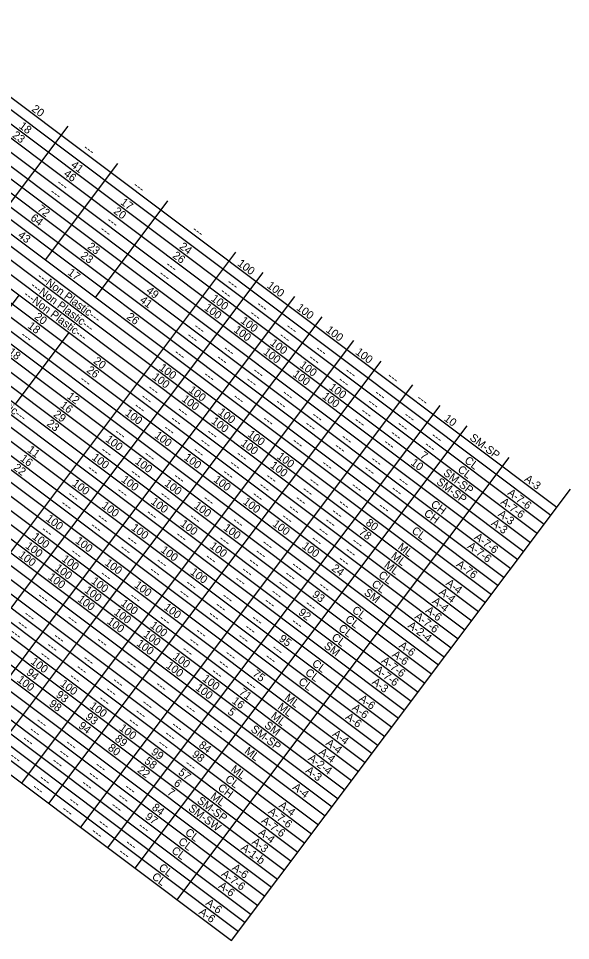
# Model space of a CAD drawing. Extents: x 627484.2 to 627514.4, y 367972.1 to 367996.9.
# Drawn here: x 627496.37 to 627500.17, y 367972.11 to 367978.45 of the extents above; entities that cross this region are included whole.
import ezdxf

# ---------------------------------------------------------------- set-up
doc = ezdxf.new("R2010")
doc.units = 0
doc.layers.add('Default', color=7, linetype='Continuous')

msp = doc.modelspace()

# ---------------------------------------------------------------- linework, layer by layer
at = {"layer": 'Default'}
for p, q in [((627495.5986, 367978.4521), (627500.0738, 367975.0916)), ((627495.5576, 367978.3975), (627500.0329, 367975.037)), ((627495.5108, 367978.3352), (627499.986, 367974.9747)), ((627495.4639, 367978.2728), (627499.9392, 367974.9123)), ((627495.4171, 367978.2104), (627499.8924, 367974.8499)), ((627495.3703, 367978.1481), (627499.8455, 367974.7876)), ((627495.3293, 367978.0935), (627499.8045, 367974.733)), ((627495.2825, 367978.0311), (627499.7577, 367974.6706)), ((627495.1946, 367977.9142), (627499.6699, 367974.5537)), ((627495.2356, 367977.9687), (627499.7109, 367974.6082)), ((627495.1478, 367977.8518), (627499.623, 367974.4913)), ((627495.1068, 367977.7972), (627499.5821, 367974.4367)), ((627495.06, 367977.7348), (627499.5352, 367974.3743)), ((627495.0131, 367977.6725), (627499.4884, 367974.312)), ((627495.0743, 367975.5294), (627496.7136, 367977.7124)), ((627494.9663, 367977.6101), (627499.4416, 367974.2496)), ((627494.9195, 367977.5477), (627499.3947, 367974.1872)), ((627494.8726, 367977.4853), (627499.3479, 367974.1248)), ((627494.8258, 367977.423), (627499.301, 367974.0625)), ((627496.559, 367976.7921), (627497.0566, 367977.4548)), ((627494.7848, 367977.3684), (627499.2601, 367974.0079)), ((627494.738, 367977.306), (627499.2132, 367973.9455)), ((627494.6911, 367977.2437), (627499.1664, 367973.8831)), ((627494.6443, 367977.1813), (627499.1196, 367973.8208)), ((627496.902, 367976.5345), (627497.3997, 367977.1972)), ((627494.5975, 367977.1189), (627499.0727, 367973.7584)), ((627494.5506, 367977.0565), (627499.0259, 367973.696)), ((627494.5097, 367977.002), (627498.9849, 367973.6415)), ((627494.4628, 367976.9396), (627498.9381, 367973.5791)), ((627494.416, 367976.8772), (627498.8912, 367973.5167)), ((627496.2282, 367974.6629), (627497.8675, 367976.846)), ((627494.3691, 367976.8148), (627498.8444, 367973.4543)), ((627494.3282, 367976.7603), (627498.8034, 367973.3998)), ((627496.4153, 367974.5224), (627498.0546, 367976.7054)), ((627494.2813, 367976.6979), (627498.7566, 367973.3374)), ((627494.2345, 367976.6355), (627498.7097, 367973.275)), ((627494.1877, 367976.5731), (627498.6629, 367973.2126)), ((627496.0087, 367976.0592), (627496.3775, 367976.5504)), ((627496.6336, 367974.3585), (627498.2729, 367976.5415)), ((627494.1408, 367976.5108), (627498.6161, 367973.1503)), ((627494.053, 367976.3938), (627498.5282, 367973.0333)), ((627494.094, 367976.4484), (627498.5692, 367973.0879)), ((627496.8207, 367974.218), (627498.46, 367976.401)), ((627494.0062, 367976.3314), (627498.4814, 367972.9709)), ((627493.9593, 367976.2691), (627498.4346, 367972.9086)), ((627496.3517, 367975.8016), (627496.7205, 367976.2928)), ((627493.9125, 367976.2067), (627498.3877, 367972.8462)), ((627497.039, 367974.054), (627498.6783, 367976.2371)), ((627493.8657, 367976.1443), (627498.3409, 367972.7838)), ((627493.8188, 367976.082), (627498.2941, 367972.7215)), ((627497.2262, 367973.9135), (627498.8654, 367976.0966)), ((627493.772, 367976.0196), (627498.2472, 367972.6591)), ((627493.7251, 367975.9572), (627498.2004, 367972.5967)), ((627493.6783, 367975.8948), (627498.1536, 367972.5343)), ((627497.4445, 367973.7496), (627499.0837, 367975.9326)), ((627493.6373, 367975.8403), (627498.1126, 367972.4798)), ((627493.5905, 367975.7779), (627498.0657, 367972.4174)), ((627497.6316, 367973.6091), (627499.2709, 367975.7921)), ((627493.5437, 367975.7155), (627498.0189, 367972.355)), ((627493.4968, 367975.6531), (627497.9721, 367972.2926)), ((627497.8187, 367973.4686), (627499.458, 367975.6516)), ((627493.4558, 367975.5986), (627497.9311, 367972.2381)), ((627493.409, 367975.5362), (627497.8842, 367972.1757)), ((627493.3622, 367975.4738), (627497.8374, 367972.1133)), ((627498.1072, 367973.252), (627499.7464, 367975.435)), ((627498.4814, 367972.9709), (627500.1675, 367975.2164)), ((627495.7713, 367973.6648), (627496.4153, 367974.5224)), ((627495.9896, 367973.5008), (627496.6336, 367974.3585)), ((627496.1767, 367973.3603), (627496.8207, 367974.218)), ((627496.395, 367973.1964), (627497.039, 367974.054)), ((627496.5822, 367973.0559), (627497.2262, 367973.9135)), ((627496.8005, 367972.892), (627497.4445, 367973.7496)), ((627496.9876, 367972.7515), (627497.6316, 367973.6091)), ((627497.1747, 367972.611), (627497.8187, 367973.4686)), ((627497.7719, 367973.4062), (627498.4346, 367972.9086)), ((627497.4632, 367972.3943), (627498.1072, 367973.252)), ((627497.8374, 367972.1133), (627498.4814, 367972.9709))]:
    msp.add_line(p, q, dxfattribs=at)

# ---------------------------------------------------------------- texts
for s, p in [('20', (627496.4591, 367977.8204)), ('18', (627496.372, 367977.7029)), ('23', (627496.326, 367977.6399)), ('---', (627496.814, 367977.5539)), ('46', (627496.6793, 367977.3746)), ('41', (627496.7288, 367977.4349)), ('---', (627496.6325, 367977.3122)), ('---', (627497.157, 367977.2963)), ('---', (627496.5857, 367977.2498)), ('72', (627496.4979, 367977.1328)), ('20', (627497.0222, 367977.1171)), ('17', (627497.0694, 367977.1792)), ('64', (627496.4508, 367977.0706)), ('---', (627496.9755, 367977.0546)), ('43', (627496.3646, 367976.9525)), ('---', (627496.9287, 367976.9922)), ('---', (627497.5625, 367976.9918)), ('23', (627496.8423, 367976.8742)), ('24', (627497.4744, 367976.875)), ('23', (627496.7954, 367976.8118)), ('26', (627497.4277, 367976.8126)), ('100', (627497.8735, 367976.7583)), ('17', (627496.7064, 367976.6958)), ('---', (627497.3341, 367976.6878)), ('---', (627497.381, 367976.7501)), ('---Non Plastic---', (627496.4976, 367976.6697)), ('---', (627497.8021, 367976.629)), ('---Non Plastic---', (627496.4508, 367976.6073)), ('49', (627497.2464, 367976.5708)), ('---', (627497.7553, 367976.5666)), ('100', (627498.0762, 367976.606)), ('---Non Plastic---', (627496.404, 367976.5449)), ('41', (627497.2021, 367976.5064)), ('100', (627497.692, 367976.5166)), ('100', (627497.6452, 367976.4542)), ('---', (627498.0048, 367976.4768)), ('100', (627498.2789, 367976.4538)), ('20', (627496.4778, 367976.392)), ('26', (627497.1116, 367976.3915)), ('100', (627497.8947, 367976.3643)), ('---', (627497.958, 367976.4144)), ('18', (627496.4316, 367976.3291)), ('---', (627497.5738, 367976.3249)), ('100', (627497.8479, 367976.302)), ('---', (627498.2075, 367976.3245)), ('100', (627498.4816, 367976.3016)), ('---', (627496.3842, 367976.2671)), ('---', (627497.5269, 367976.2625)), ('---', (627498.1607, 367976.2622)), ('100', (627498.0974, 367976.2121)), ('18', (627496.297, 367976.1498)), ('---', (627497.4391, 367976.1456)), ('---', (627497.7765, 367976.1727)), ('100', (627498.0506, 367976.1497)), ('---', (627498.4102, 367976.1723)), ('100', (627498.6844, 367976.1494)), ('20', (627496.8832, 367976.0875)), ('100', (627497.3349, 367976.041)), ('---', (627497.7296, 367976.1103)), ('100', (627498.3002, 367976.0599)), ('---', (627498.3634, 367976.11)), ('---Non Plastic---', (627495.9883, 367975.9914)), ('26', (627496.8364, 367976.0251)), ('100', (627497.2881, 367975.9786)), ('---', (627497.6418, 367975.9934)), ('---', (627497.9792, 367976.0205)), ('100', (627498.2533, 367975.9975)), ('---', (627498.6129, 367976.0201)), ('---', (627496.7897, 367975.9627)), ('---', (627497.9324, 367975.9581)), ('---', (627498.5661, 367975.9577)), ('---', (627498.9035, 367975.9848)), ('---', (627497.2576, 367975.9039)), ('100', (627497.5376, 367975.8887)), ('---', (627498.1819, 367975.8683)), ('100', (627498.5029, 367975.9077)), ('---', (627498.8157, 367975.8679)), ('12', (627496.7019, 367975.8457)), ('---', (627497.2108, 367975.8415)), ('100', (627497.4908, 367975.8264)), ('---', (627497.8445, 367975.8412)), ('---', (627498.1351, 367975.8059)), ('100', (627498.456, 367975.8453)), ('---', (627498.7688, 367975.8055)), ('---', (627499.1062, 367975.8326)), ('29', (627496.6082, 367975.7209)), ('16', (627496.6549, 367975.7834)), ('100', (627497.1007, 367975.7291)), ('---', (627497.164, 367975.7792)), ('---', (627497.4603, 367975.7517)), ('100', (627497.7403, 367975.7365)), ('---', (627498.722, 367975.7431)), ('23', (627496.5627, 367975.6576)), ('---', (627497.4135, 367975.6893)), ('100', (627497.6935, 367975.6742)), ('---', (627498.0472, 367975.6889)), ('---', (627498.3846, 367975.716)), ('---', (627498.6751, 367975.6808)), ('---', (627499.0184, 367975.7157)), ('10', (627499.2931, 367975.6922)), ('---', (627497.3667, 367975.6269)), ('---', (627498.3378, 367975.6537)), ('---', (627498.9715, 367975.6533)), ('100', (627496.9661, 367975.5498)), ('---', (627497.0293, 367975.5998)), ('100', (627497.3034, 367975.5769)), ('---', (627497.663, 367975.5995)), ('100', (627497.943, 367975.5843)), ('---', (627498.5873, 367975.5638)), ('---', (627498.9247, 367975.5909)), ('---', (627499.2055, 367975.5752)), ('SM-SP', (627499.4696, 367975.5598)), ('11', (627496.4293, 367975.4773)), ('---', (627497.6162, 367975.5371)), ('100', (627497.8962, 367975.5219)), ('---', (627498.25, 367975.5367)), ('---', (627498.5405, 367975.5015)), ('---', (627498.8779, 367975.5286)), ('---', (627499.1586, 367975.5128)), ('16', (627496.3798, 367975.417)), ('100', (627496.8724, 367975.425)), ('---', (627496.9356, 367975.4751)), ('---', (627497.232, 367975.4476)), ('100', (627497.5061, 367975.4247)), ('---', (627497.5694, 367975.4747)), ('---', (627497.8658, 367975.4472)), ('100', (627498.1457, 367975.4321)), ('7', (627499.1282, 367975.4381)), ('CL', (627499.4337, 367975.4038)), ('22', (627496.333, 367975.3545)), ('100', (627497.1688, 367975.3976)), ('---', (627497.8189, 367975.3849)), ('100', (627498.0989, 367975.3697)), ('---', (627498.4527, 367975.3845)), ('---', (627498.79, 367975.4116)), ('10', (627499.0648, 367975.3882)), ('CL', (627499.3868, 367975.3415)), ('---', (627496.842, 367975.3503)), ('---', (627497.1383, 367975.3229)), ('---', (627497.4347, 367975.2954)), ('---', (627497.7721, 367975.3225)), ('---', (627498.0685, 367975.295)), ('---', (627498.7432, 367975.3492)), ('SM-SP', (627499.2881, 367975.3181)), ('100', (627496.7377, 367975.2457)), ('100', (627497.0751, 367975.2728)), ('100', (627497.3715, 367975.2453)), ('100', (627497.7088, 367975.2724)), ('---', (627498.0216, 367975.2327)), ('---', (627498.3649, 367975.2676)), ('---', (627498.6554, 367975.2323)), ('---', (627498.9772, 367975.2711)), ('SM-SP', (627499.2412, 367975.2557)), ('A-3', (627499.8458, 367975.2772)), ('---', (627496.7073, 367975.171)), ('---', (627497.0447, 367975.1981)), ('---', (627497.341, 367975.1707)), ('---', (627497.9748, 367975.1703)), ('---', (627498.318, 367975.2052)), ('---', (627498.9303, 367975.2087)), ('A-7-6', (627499.7295, 367975.1817)), ('---', (627496.6605, 367975.1086)), ('100', (627496.9404, 367975.0935)), ('100', (627497.2778, 367975.1206)), ('100', (627497.5742, 367975.0931)), ('---', (627497.6374, 367975.1432)), ('100', (627497.9116, 367975.1202)), ('---', (627498.2712, 367975.1428)), ('---', (627498.5676, 367975.1153)), ('CH', (627499.2017, 367975.1025)), ('A-7-6', (627499.6826, 367975.1193)), ('---', (627497.2474, 367975.0459)), ('---', (627498.2243, 367975.0804)), ('---', (627498.5207, 367975.053)), ('---', (627498.8425, 367975.0918)), ('CH', (627499.1549, 367975.0401)), ('A-3', (627499.6643, 367975.0355)), ('100', (627496.5562, 367975.004)), ('---', (627496.91, 367975.0188)), ('100', (627497.4805, 367974.9684)), ('---', (627497.5438, 367975.0184)), ('---', (627497.8401, 367974.991)), ('100', (627498.1143, 367974.968)), ('---', (627498.1775, 367975.0181)), ('---', (627498.4739, 367974.9906)), ('80', (627498.7545, 367974.9749)), ('A-3', (627499.6175, 367974.9732)), ('---', (627496.5258, 367974.9293)), ('---', (627496.8632, 367974.9564)), ('100', (627497.1432, 367974.9413)), ('100', (627497.7769, 367974.9409)), ('---', (627498.4271, 367974.9282)), ('78', (627498.7084, 367974.912)), ('CL', (627499.0707, 367974.9204)), ('100', (627496.4626, 367974.8793)), ('100', (627496.759, 367974.8518)), ('---', (627497.1127, 367974.8666)), ('---', (627497.4501, 367974.8937)), ('---', (627497.7465, 367974.8662)), ('---', (627498.3802, 367974.8658)), ('---', (627498.661, 367974.8501)), ('A-7-6', (627499.5012, 367974.8776)), ('100', (627496.4157, 367974.8169)), ('---', (627497.0659, 367974.8042)), ('100', (627497.3459, 367974.7891)), ('100', (627497.6832, 367974.8162)), ('---', (627498.0429, 367974.8387)), ('100', (627498.317, 367974.8158)), ('---', (627498.6142, 367974.7877)), ('ML', (627498.9756, 367974.8089)), ('A-7-6', (627499.4543, 367974.8153)), ('100', (627496.3689, 367974.7545)), ('100', (627496.6653, 367974.7271)), ('---', (627496.7285, 367974.7771)), ('---', (627497.6528, 367974.7415)), ('---', (627497.996, 367974.7764)), ('---', (627498.5673, 367974.7253)), ('ML', (627498.9288, 367974.7465)), ('100', (627496.6184, 367974.6647)), ('100', (627496.9617, 367974.6996)), ('---', (627497.3154, 367974.7144)), ('---', (627497.9492, 367974.714)), ('---', (627498.2456, 367974.6865)), ('24', (627498.5203, 367974.6631)), ('ML', (627498.882, 367974.6842)), ('A-76', (627499.3773, 367974.6902)), ('100', (627496.5716, 367974.6023)), ('---', (627496.9312, 367974.6249)), ('---', (627497.2686, 367974.652)), ('100', (627497.5486, 367974.6368)), ('---', (627497.9023, 367974.6516)), ('---', (627498.1987, 367974.6242)), ('CL', (627498.8423, 367974.6164)), ('100', (627496.868, 367974.5748)), ('100', (627497.1644, 367974.5474)), ('---', (627497.5181, 367974.5621)), ('---', (627497.8555, 367974.5893)), ('---', (627498.1519, 367974.5618)), ('---', (627498.4327, 367974.546)), ('CL', (627498.7955, 367974.554)), ('A-4', (627499.3056, 367974.5611)), ('---', (627496.5002, 367974.473)), ('100', (627496.8212, 367974.5125)), ('---', (627497.1339, 367974.4727)), ('---', (627497.4713, 367974.4998)), ('---', (627497.7677, 367974.4723)), ('---', (627498.1051, 367974.4994)), ('93', (627498.3872, 367974.4826)), ('SM', (627498.7432, 367974.4957)), ('A-4', (627499.2588, 367974.4988)), ('100', (627496.7743, 367974.4501)), ('100', (627497.0707, 367974.4226)), ('100', (627497.3671, 367974.3951)), ('---', (627497.7209, 367974.4099)), ('---', (627498.0582, 367974.437)), ('---', (627498.339, 367974.4213)), ('A-4', (627499.2119, 367974.4364)), ('---', (627496.4065, 367974.3483)), ('100', (627497.0239, 367974.3602)), ('---', (627497.674, 367974.3476)), ('92', (627498.2922, 367974.3589)), ('CL', (627498.6609, 367974.3747)), ('A-7-6', (627499.0913, 367974.3319)), ('A-6', (627499.1652, 367974.3739)), ('---', (627496.3597, 367974.2859)), ('---', (627496.7029, 367974.3208)), ('100', (627496.977, 367974.2979)), ('100', (627497.2734, 367974.2704)), ('---', (627497.3367, 367974.3205)), ('---', (627497.9704, 367974.3201)), ('---', (627498.2453, 367974.2965)), ('CL', (627498.614, 367974.3123)), ('A-2-4', (627499.0444, 367974.2696)), ('---', (627496.3128, 367974.2236)), ('100', (627497.2266, 367974.208)), ('---', (627497.5862, 367974.2306)), ('---', (627497.9236, 367974.2577)), ('CL', (627498.5672, 367974.2499)), ('---', (627496.6092, 367974.1961)), ('---', (627496.9056, 367974.1686)), ('100', (627497.1797, 367974.1457)), ('---', (627497.5394, 367974.1682)), ('---', (627497.8767, 367974.1953)), ('95', (627498.1583, 367974.179)), ('CL', (627498.5203, 367974.1876)), ('---', (627496.5624, 367974.1337)), ('---', (627497.4925, 367974.1059)), ('---', (627498.1107, 367974.1172)), ('SM', (627498.4681, 367974.1293)), ('A-6', (627498.9837, 367974.1322)), ('100', (627496.4523, 367974.0213)), ('---', (627496.5156, 367974.0713)), ('---', (627496.8119, 367974.0439)), ('100', (627497.4293, 367974.0558)), ('---', (627497.7889, 367974.0784)), ('---', (627498.0638, 367974.0548)), ('A-7-6', (627498.863, 367974.0278)), ('A-6', (627498.9369, 367974.0698)), ('94', (627496.4217, 367973.9467)), ('---', (627496.7651, 367973.9815)), ('---', (627497.1083, 367974.0164)), ('100', (627497.3825, 367973.9934)), ('---', (627497.7421, 367974.016)), ('CL', (627498.3389, 367973.9459)), ('CL', (627498.3857, 367974.0082)), ('A-7-6', (627498.8162, 367973.9654)), ('100', (627496.3586, 367973.8965)), ('---', (627496.7183, 367973.9191)), ('100', (627497.632, 367973.9036)), ('---', (627497.6952, 367973.9536)), ('75', (627497.9769, 367973.9373)), ('CL', (627498.292, 367973.8835)), ('100', (627496.655, 367973.8691)), ('---', (627497.0147, 367973.8916)), ('---', (627497.311, 367973.8642)), ('100', (627497.5852, 367973.8412)), ('71', (627497.885, 367973.8111)), ('---', (627497.9292, 367973.8755)), ('A-3', (627498.7979, 367973.8816)), ('93', (627496.626, 367973.7933)), ('---', (627496.9678, 367973.8293)), ('ML', (627498.197, 367973.772)), ('A-6', (627498.7086, 367973.7658)), ('98', (627496.5783, 367973.7316)), ('100', (627496.8577, 367973.7168)), ('---', (627496.921, 367973.7669)), ('---', (627497.2174, 367973.7394)), ('---', (627497.5138, 367973.712)), ('16', (627497.8355, 367973.7508)), ('ML', (627498.1501, 367973.7096)), ('A-6', (627498.6617, 367973.7034)), ('93', (627496.8287, 367973.6411)), ('---', (627497.1705, 367973.6771)), ('5', (627497.8058, 367973.6756)), ('ML', (627498.1033, 367973.6472)), ('A-6', (627498.6149, 367973.641)), ('---', (627496.4899, 367973.615)), ('94', (627496.7803, 367973.5799)), ('---', (627497.1237, 367973.6147)), ('---', (627497.4201, 367973.5872)), ('SM', (627498.0582, 367973.5835)), ('---', (627496.4431, 367973.5527)), ('100', (627497.0605, 367973.5646)), ('---', (627497.3732, 367973.5248)), ('---', (627497.7009, 367973.5714)), ('SM-SP', (627497.9649, 367973.556)), ('A-4', (627498.527, 367973.5242)), ('---', (627496.3963, 367973.4903)), ('---', (627496.6927, 367973.4628)), ('89', (627497.0301, 367973.4899)), ('---', (627497.3264, 367973.4625)), ('84', (627497.607, 367973.4468)), ('A-4', (627498.4801, 367973.4618)), ('---', (627496.6458, 367973.4005)), ('80', (627496.983, 367973.4277)), ('99', (627497.2796, 367973.4)), ('98', (627497.5609, 367973.3839)), ('ML', (627497.9218, 367973.4055)), ('A-4', (627498.4333, 367973.3994)), ('---', (627496.3085, 367973.3734)), ('---', (627496.599, 367973.3381)), ('58', (627497.2333, 367973.3373)), ('A-2-4', (627498.3594, 367973.3574)), ('---', (627496.8954, 367973.3106)), ('22', (627497.1859, 367973.2753)), ('57', (627497.4668, 367973.2595)), ('---', (627497.5135, 367973.322)), ('ML', (627497.8281, 367973.2808)), ('A-3', (627498.3412, 367973.2735)), ('---', (627496.5112, 367973.2211)), ('---', (627496.8485, 367973.2482)), ('6', (627497.436, 367973.1851)), ('CL', (627497.7885, 367973.213)), ('---', (627496.4643, 367973.1588)), ('---', (627496.8017, 367973.1859)), ('---', (627497.0981, 367973.1584)), ('7', (627497.3894, 367973.1225)), ('CH', (627497.7381, 367973.1533)), ('A-4', (627498.2518, 367973.1577)), ('---', (627497.0512, 367973.096)), ('SM-SP', (627497.5961, 367973.0649)), ('ML', (627497.6876, 367973.0937)), ('---', (627496.7139, 367973.0689)), ('---', (627497.0044, 367973.0336)), ('84', (627497.285, 367973.018)), ('SM-SW', (627497.5358, 367973.0126)), ('A-4', (627498.1581, 367973.033)), ('---', (627496.667, 367973.0065)), ('97', (627497.2385, 367972.9554)), ('A-7-6', (627498.0844, 367972.9909)), ('---', (627496.9166, 367972.9167)), ('---', (627497.1915, 367972.8931)), ('A-7-6', (627498.0375, 367972.9285)), ('---', (627496.8698, 367972.8543)), ('CL', (627497.5134, 367972.8465)), ('A-4', (627498.0176, 367972.8459)), ('---', (627497.1037, 367972.7762)), ('CL', (627497.4665, 367972.7842)), ('A-3', (627497.9724, 367972.7823)), ('---', (627497.0569, 367972.7138)), ('CL', (627497.4197, 367972.7218)), ('A-1-b', (627497.8969, 367972.7414)), ('CL', (627497.3319, 367972.6049)), ('A-7-6', (627497.7624, 367972.562)), ('A-6', (627497.8363, 367972.6041)), ('CL', (627497.285, 367972.5425)), ('A-6', (627497.7426, 367972.4793)), ('A-6', (627497.6079, 367972.3)), ('A-6', (627497.6548, 367972.3624))]:
    msp.add_text(s, height=0.055, rotation=323.09678, dxfattribs=at).set_placement(p)

doc.saveas('drawing.dxf')
